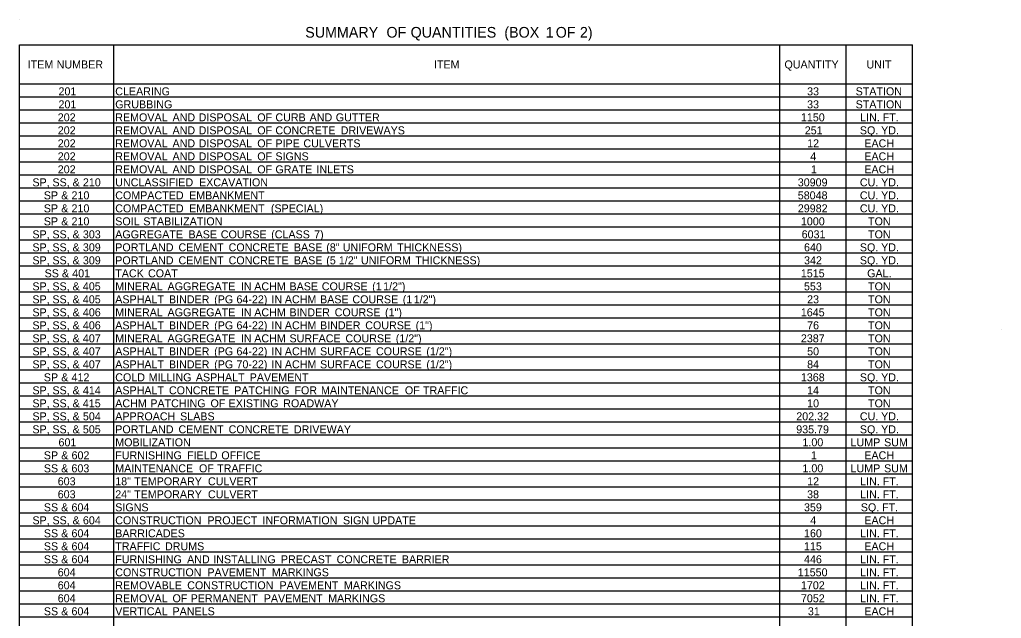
# Model space of a CAD drawing. Extents: x 1197542 to 1207068, y 230488 to 237324.
# Drawn here: x 1205581 to 1206317, y 232261 to 232710 of the extents above; entities that cross this region are included whole.
import ezdxf

# ---------------------------------------------------------------- set-up
doc = ezdxf.new("R2010")
doc.units = 0
doc.layers.add('Default', color=7, linetype='Continuous')

msp = doc.modelspace()

# ---------------------------------------------------------------- linework, layer by layer
at = {"layer": 'Default'}
for p, q in [((1205581.41, 232709.91), (1205581.41, 232709.91)), ((1205581.41, 232690.9), (1205652.09, 232690.9)), ((1205581.41, 232690.9), (1206250.74, 232690.9)), ((1205581.41, 231823.15), (1205581.41, 232690.9)), ((1205652.09, 231823.15), (1205652.09, 232690.9)), ((1206151.29, 231823.15), (1206151.29, 232690.9)), ((1206201.02, 231823.15), (1206201.02, 232690.9)), ((1206201.02, 231823.15), (1206201.02, 232690.9)), ((1206250.74, 231823.15), (1206250.74, 232690.9)), ((1205581.41, 232661.65), (1206250.74, 232661.65)), ((1205652.09, 231823.15), (1205652.09, 232661.65)), ((1206151.29, 231823.15), (1206151.29, 232661.65)), ((1205581.41, 232651.9), (1206250.74, 232651.9)), ((1205581.41, 232642.15), (1206250.74, 232642.15)), ((1205581.41, 232632.4), (1206250.74, 232632.4)), ((1205581.41, 232622.65), (1206250.74, 232622.65)), ((1205581.41, 232612.9), (1206250.74, 232612.9)), ((1205581.41, 232603.15), (1206250.74, 232603.15)), ((1205581.41, 232593.4), (1206250.74, 232593.4)), ((1205581.41, 232583.65), (1206250.74, 232583.65)), ((1205581.41, 232573.9), (1206250.74, 232573.9)), ((1205581.41, 232564.15), (1206250.74, 232564.15)), ((1205581.41, 232554.4), (1206250.74, 232554.4)), ((1205581.41, 232544.65), (1206250.74, 232544.65)), ((1205581.41, 232534.9), (1206250.74, 232534.9)), ((1205581.41, 232525.15), (1206250.74, 232525.15)), ((1205581.41, 232515.4), (1206250.74, 232515.4)), ((1205581.41, 232505.65), (1206250.74, 232505.65)), ((1205581.41, 232495.9), (1206250.74, 232495.9)), ((1205581.41, 232486.15), (1206250.74, 232486.15)), ((1206317.3, 232477.8), (1206317.3, 232477.8)), ((1205581.41, 232476.4), (1206250.74, 232476.4)), ((1205581.41, 232466.65), (1206250.74, 232466.65)), ((1205581.41, 232456.9), (1206250.74, 232456.9)), ((1205581.41, 232447.15), (1206250.74, 232447.15)), ((1205581.41, 232437.4), (1206250.74, 232437.4)), ((1205581.41, 232427.65), (1206250.74, 232427.65)), ((1205581.41, 232417.9), (1206250.74, 232417.9)), ((1205581.41, 232408.15), (1206250.74, 232408.15)), ((1205581.41, 232398.4), (1206250.74, 232398.4)), ((1205581.41, 232388.65), (1206250.74, 232388.65)), ((1205581.41, 232378.9), (1206250.74, 232378.9)), ((1205581.41, 232369.15), (1206250.74, 232369.15)), ((1205581.41, 232359.4), (1206250.74, 232359.4)), ((1205581.41, 232349.65), (1206250.74, 232349.65)), ((1205581.41, 232339.9), (1206250.74, 232339.9)), ((1205581.41, 232330.15), (1206250.74, 232330.15)), ((1205581.41, 232320.4), (1206250.74, 232320.4)), ((1205581.41, 232310.65), (1206250.74, 232310.65)), ((1205581.41, 232300.9), (1206250.74, 232300.9)), ((1205581.41, 232291.15), (1206250.74, 232291.15)), ((1205581.41, 232281.4), (1206250.74, 232281.4)), ((1205581.41, 232271.65), (1206250.74, 232271.65)), ((1205581.41, 232261.9), (1206250.74, 232261.9))]:
    msp.add_line(p, q, dxfattribs=at)

# ---------------------------------------------------------------- texts
for s, height, p in [(' SUMMARY', 8, (1205792.52, 232696.41)), (' OF', 8, (1205853.4, 232696.41)), (' QUANTITIES', 8, (1205871.51, 232696.41)), (' (BOX', 8, (1205941.76, 232696.41)), (' 1', 8, (1205972.79, 232696.41)), (' OF', 8, (1205980.3, 232696.41)), (' 2)', 8, (1205998.41, 232696.41)), ('ITEM', 6, (1205587.49, 232673.28)), (' NUMBER', 6, (1205606.92, 232673.28)), ('ITEM', 6, (1205891.98, 232673.28)), ('QUANTITY', 6, (1206154.72, 232673.28)), ('UNIT', 6, (1206216.19, 232673.28)), ('201', 6, (1205610.53, 232653.1)), ('CLEARING', 6, (1205653.07, 232653.1)), ('33', 6, (1206171.69, 232653.1)), ('STATION', 6, (1206208.06, 232653.1)), ('201', 6, (1205610.53, 232643.35)), ('GRUBBING', 6, (1205653.07, 232643.35)), ('33', 6, (1206171.69, 232643.35)), ('STATION', 6, (1206208.06, 232643.35)), ('202', 6, (1205609.98, 232633.6)), ('REMOVAL', 6, (1205653.07, 232633.6)), (' AND', 6, (1205693.77, 232633.6)), (' DISPOSAL', 6, (1205713.35, 232633.6)), (' OF', 6, (1205757.32, 232633.6)), (' CURB', 6, (1205770.9, 232633.6)), (' AND', 6, (1205796.54, 232633.6)), (' GUTTER', 6, (1205816.12, 232633.6)), ('1150', 6, (1206167.04, 232633.6)), ('LIN.', 6, (1206211.48, 232633.6)), (' FT.', 6, (1206226.12, 232633.6)), ('202', 6, (1205609.98, 232623.85)), ('REMOVAL', 6, (1205653.07, 232623.85)), (' AND', 6, (1205693.77, 232623.85)), (' DISPOSAL', 6, (1205713.35, 232623.85)), (' OF', 6, (1205757.32, 232623.85)), (' CONCRETE', 6, (1205770.9, 232623.85)), (' DRIVEWAYS', 6, (1205819.83, 232623.85)), ('251', 6, (1206169.94, 232623.85)), ('SQ.', 6, (1206211.24, 232623.85)), (' YD.', 6, (1206224.95, 232623.85)), ('202', 6, (1205609.98, 232614.1)), ('REMOVAL', 6, (1205653.07, 232614.1)), (' AND', 6, (1205693.77, 232614.1)), (' DISPOSAL', 6, (1205713.35, 232614.1)), (' OF', 6, (1205757.32, 232614.1)), (' PIPE', 6, (1205770.9, 232614.1)), (' CULVERTS', 6, (1205791.89, 232614.1)), ('12', 6, (1206171.72, 232614.1)), ('EACH', 6, (1206214.57, 232614.1)), ('202', 6, (1205609.98, 232604.35)), ('REMOVAL', 6, (1205653.07, 232604.35)), (' AND', 6, (1205693.77, 232604.35)), (' DISPOSAL', 6, (1205713.35, 232604.35)), (' OF', 6, (1205757.32, 232604.35)), (' SIGNS', 6, (1205770.9, 232604.35)), ('4', 6, (1206174.03, 232604.35)), ('EACH', 6, (1206214.57, 232604.35)), ('202', 6, (1205609.98, 232594.6)), ('REMOVAL', 6, (1205653.07, 232594.6)), (' AND', 6, (1205693.77, 232594.6)), (' DISPOSAL', 6, (1205713.35, 232594.6)), (' OF', 6, (1205757.32, 232594.6)), (' GRATE', 6, (1205770.9, 232594.6)), (' INLETS', 6, (1205801.67, 232594.6)), ('1', 6, (1206174.6, 232594.6)), ('EACH', 6, (1206214.57, 232594.6)), ('SP,', 6, (1205591, 232584.85)), (' SS,', 6, (1205603.77, 232584.85)), (' &', 6, (1205618.86, 232584.85)), (' 210', 6, (1205626.59, 232584.85)), ('UNCLASSIFIED', 6, (1205653.07, 232584.85)), (' EXCAVATION', 6, (1205713.65, 232584.85)), ('30909', 6, (1206164.69, 232584.85)), ('CU.', 6, (1206211.24, 232584.85)), (' YD.', 6, (1206224.95, 232584.85)), ('SP', 6, (1205599.52, 232575.1)), (' &', 6, (1205610.34, 232575.1)), (' 210', 6, (1205618.07, 232575.1)), ('COMPACTED', 6, (1205653.07, 232575.1)), (' EMBANKMENT', 6, (1205706.19, 232575.1)), ('58048', 6, (1206164.69, 232575.1)), ('CU.', 6, (1206211.24, 232575.1)), (' YD.', 6, (1206224.95, 232575.1)), ('SP', 6, (1205599.52, 232565.35)), (' &', 6, (1205610.34, 232565.35)), (' 210', 6, (1205618.07, 232565.35)), ('COMPACTED', 6, (1205653.07, 232565.35)), (' EMBANKMENT', 6, (1205706.19, 232565.35)), (' (SPECIAL)', 6, (1205767.51, 232565.35)), ('29982', 6, (1206164.73, 232565.35)), ('CU.', 6, (1206211.24, 232565.35)), (' YD.', 6, (1206224.95, 232565.35)), ('SP', 6, (1205599.52, 232555.6)), (' &', 6, (1205610.34, 232555.6)), (' 210', 6, (1205618.07, 232555.6)), ('SOIL', 6, (1205653.07, 232555.6)), (' STABILIZATION', 6, (1205671.87, 232555.6)), ('1000', 6, (1206167.04, 232555.6)), ('TON', 6, (1206217.37, 232555.6)), ('SP,', 6, (1205590.99, 232545.85)), (' SS,', 6, (1205603.76, 232545.85)), (' &', 6, (1205618.85, 232545.85)), (' 303', 6, (1205626.58, 232545.85)), ('AGGREGATE', 6, (1205653.07, 232545.85)), (' BASE', 6, (1205705.73, 232545.85)), (' COURSE', 6, (1205729.98, 232545.85)), (' (CLASS', 6, (1205767.74, 232545.85)), (' 7)', 6, (1205799.91, 232545.85)), ('6031', 6, (1206167.61, 232545.85)), ('TON', 6, (1206217.37, 232545.85)), ('SP,', 6, (1205590.98, 232536.1)), (' SS,', 6, (1205603.75, 232536.1)), (' &', 6, (1205618.85, 232536.1)), (' 309', 6, (1205626.58, 232536.1)), ('PORTLAND', 6, (1205653.07, 232536.1)), (' CEMENT', 6, (1205698.27, 232536.1)), (' CONCRETE', 6, (1205735.83, 232536.1)), (' BASE', 6, (1205784.76, 232536.1)), (' (8"', 6, (1205809.01, 232536.1)), (' UNIFORM', 6, (1205821.37, 232536.1)), (' THICKNESS)', 6, (1205862.19, 232536.1)), ('640', 6, (1206169.37, 232536.1)), ('SQ.', 6, (1206211.24, 232536.1)), (' YD.', 6, (1206224.95, 232536.1)), ('SP,', 6, (1205590.98, 232526.35)), (' SS,', 6, (1205603.75, 232526.35)), (' &', 6, (1205618.85, 232526.35)), (' 309', 6, (1205626.58, 232526.35)), ('PORTLAND', 6, (1205653.07, 232526.35)), (' CEMENT', 6, (1205698.27, 232526.35)), (' CONCRETE', 6, (1205735.83, 232526.35)), (' BASE', 6, (1205784.76, 232526.35)), (' (5', 6, (1205809.01, 232526.35)), (' 1/2"', 6, (1205818.46, 232526.35)), (' UNIFORM', 6, (1205835.02, 232526.35)), (' THICKNESS)', 6, (1205875.83, 232526.35)), ('342', 6, (1206169.39, 232526.35)), ('SQ.', 6, (1206211.24, 232526.35)), (' YD.', 6, (1206224.95, 232526.35)), ('SS', 6, (1205600.13, 232516.6)), (' &', 6, (1205610.87, 232516.6)), (' 401', 6, (1205618.6, 232516.6)), ('TACK', 6, (1205653.07, 232516.6)), (' COAT', 6, (1205675.41, 232516.6)), ('1515', 6, (1206167, 232516.6)), ('GAL.', 6, (1206216.7, 232516.6)), ('SP,', 6, (1205590.97, 232506.85)), (' SS,', 6, (1205603.73, 232506.85)), (' &', 6, (1205618.83, 232506.85)), (' 405', 6, (1205626.56, 232506.85)), ('MINERAL', 6, (1205653.07, 232506.85)), (' AGGREGATE', 6, (1205690.04, 232506.85)), (' IN', 6, (1205745.03, 232506.85)), (' ACHM', 6, (1205755.05, 232506.85)), (' BASE', 6, (1205781.44, 232506.85)), (' COURSE', 6, (1205805.69, 232506.85)), (' (1', 6, (1205843.44, 232506.85)), (' 1/2")', 6, (1205851.68, 232506.85)), ('553', 6, (1206169.36, 232506.85)), ('TON', 6, (1206217.37, 232506.85)), ('SP,', 6, (1205590.97, 232497.1)), (' SS,', 6, (1205603.73, 232497.1)), (' &', 6, (1205618.83, 232497.1)), (' 405', 6, (1205626.56, 232497.1)), ('ASPHALT', 6, (1205653.07, 232497.1)), (' BINDER', 6, (1205691.11, 232497.1)), (' (PG', 6, (1205725, 232497.1)), (' 64-22)', 6, (1205741.71, 232497.1)), (' IN', 6, (1205767.95, 232497.1)), (' ACHM', 6, (1205777.97, 232497.1)), (' BASE', 6, (1205804.36, 232497.1)), (' COURSE', 6, (1205828.61, 232497.1)), (' (1', 6, (1205866.36, 232497.1)), (' 1/2")', 6, (1205874.6, 232497.1)), ('23', 6, (1206171.69, 232497.1)), ('TON', 6, (1206217.37, 232497.1)), ('SP,', 6, (1205590.99, 232487.35)), (' SS,', 6, (1205603.76, 232487.35)), (' &', 6, (1205618.85, 232487.35)), (' 406', 6, (1205626.58, 232487.35)), ('MINERAL', 6, (1205653.07, 232487.35)), (' AGGREGATE', 6, (1205690.04, 232487.35)), (' IN', 6, (1205745.03, 232487.35)), (' ACHM', 6, (1205755.05, 232487.35)), (' BINDER', 6, (1205781.44, 232487.35)), (' COURSE', 6, (1205815.33, 232487.35)), (' (1")', 6, (1205853.08, 232487.35)), ('1645', 6, (1206167, 232487.35)), ('TON', 6, (1206217.37, 232487.35)), ('SP,', 6, (1205590.99, 232477.6)), (' SS,', 6, (1205603.76, 232477.6)), (' &', 6, (1205618.85, 232477.6)), (' 406', 6, (1205626.58, 232477.6)), ('ASPHALT', 6, (1205653.07, 232477.6)), (' BINDER', 6, (1205691.11, 232477.6)), (' (PG', 6, (1205725, 232477.6)), (' 64-22)', 6, (1205741.71, 232477.6)), (' IN', 6, (1205767.95, 232477.6)), (' ACHM', 6, (1205777.97, 232477.6)), (' BINDER', 6, (1205804.36, 232477.6)), (' COURSE', 6, (1205838.25, 232477.6)), (' (1")', 6, (1205876, 232477.6)), ('76', 6, (1206171.69, 232477.6)), ('TON', 6, (1206217.37, 232477.6)), ('SP,', 6, (1205590.99, 232467.85)), (' SS,', 6, (1205603.76, 232467.85)), (' &', 6, (1205618.85, 232467.85)), (' 407', 6, (1205626.58, 232467.85)), ('MINERAL', 6, (1205653.07, 232467.85)), (' AGGREGATE', 6, (1205690.04, 232467.85)), (' IN', 6, (1205745.03, 232467.85)), (' ACHM', 6, (1205755.05, 232467.85)), (' SURFACE', 6, (1205781.44, 232467.85)), (' COURSE', 6, (1205823.38, 232467.85)), (' (1/2")', 6, (1205861.13, 232467.85)), ('2387', 6, (1206167.03, 232467.85)), ('TON', 6, (1206217.37, 232467.85)), ('SP,', 6, (1205590.99, 232458.1)), (' SS,', 6, (1205603.76, 232458.1)), (' &', 6, (1205618.85, 232458.1)), (' 407', 6, (1205626.58, 232458.1)), ('ASPHALT', 6, (1205653.07, 232458.1)), (' BINDER', 6, (1205691.11, 232458.1)), (' (PG', 6, (1205725, 232458.1)), (' 64-22)', 6, (1205741.71, 232458.1)), (' IN', 6, (1205767.95, 232458.1)), (' ACHM', 6, (1205777.97, 232458.1)), (' SURFACE', 6, (1205804.36, 232458.1)), (' COURSE', 6, (1205846.3, 232458.1)), (' (1/2")', 6, (1205884.05, 232458.1)), ('50', 6, (1206171.7, 232458.1)), ('TON', 6, (1206217.37, 232458.1)), ('SP,', 6, (1205590.99, 232448.35)), (' SS,', 6, (1205603.76, 232448.35)), (' &', 6, (1205618.85, 232448.35)), (' 407', 6, (1205626.58, 232448.35)), ('ASPHALT', 6, (1205653.07, 232448.35)), (' BINDER', 6, (1205691.11, 232448.35)), (' (PG', 6, (1205725, 232448.35)), (' 70-22)', 6, (1205741.71, 232448.35)), (' IN', 6, (1205767.95, 232448.35)), (' ACHM', 6, (1205777.97, 232448.35)), (' SURFACE', 6, (1205804.36, 232448.35)), (' COURSE', 6, (1205846.3, 232448.35)), (' (1/2")', 6, (1205884.05, 232448.35)), ('84', 6, (1206171.7, 232448.35)), ('TON', 6, (1206217.37, 232448.35)), ('SP', 6, (1205599.54, 232438.6)), (' &', 6, (1205610.36, 232438.6)), (' 412', 6, (1205618.09, 232438.6)), ('COLD', 6, (1205653.07, 232438.6)), (' MILLING', 6, (1205675.91, 232438.6)), (' ASPHALT', 6, (1205711.25, 232438.6)), (' PAVEMENT', 6, (1205751.62, 232438.6)), ('1368', 6, (1206167.02, 232438.6)), ('SQ.', 6, (1206211.24, 232438.6)), (' YD.', 6, (1206224.95, 232438.6)), ('SP,', 6, (1205591, 232428.85)), (' SS,', 6, (1205603.77, 232428.85)), (' &', 6, (1205618.87, 232428.85)), (' 414', 6, (1205626.6, 232428.85)), ('ASPHALT', 6, (1205653.07, 232428.85)), (' CONCRETE', 6, (1205691.11, 232428.85)), (' PATCHING', 6, (1205740.04, 232428.85)), (' FOR', 6, (1205785.16, 232428.85)), (' MAINTENANCE', 6, (1205805.07, 232428.85)), (' OF', 6, (1205867.97, 232428.85)), (' TRAFFIC', 6, (1205881.56, 232428.85)), ('14', 6, (1206171.7, 232428.85)), ('TON', 6, (1206217.37, 232428.85)), ('SP,', 6, (1205590.97, 232419.1)), (' SS,', 6, (1205603.73, 232419.1)), (' &', 6, (1205618.83, 232419.1)), (' 415', 6, (1205626.56, 232419.1)), ('ACHM', 6, (1205653.07, 232419.1)), (' PATCHING', 6, (1205677.12, 232419.1)), (' OF', 6, (1205722.25, 232419.1)), (' EXISTING', 6, (1205735.83, 232419.1)), (' ROADWAY', 6, (1205776.77, 232419.1)), ('10', 6, (1206171.7, 232419.1)), ('TON', 6, (1206217.37, 232419.1)), ('SP,', 6, (1205591, 232409.35)), (' SS,', 6, (1205603.77, 232409.35)), (' &', 6, (1205618.87, 232409.35)), (' 504', 6, (1205626.6, 232409.35)), ('APPROACH', 6, (1205653.07, 232409.35)), (' SLABS', 6, (1205699.45, 232409.35)), ('202.32', 6, (1206163.56, 232409.35)), ('CU.', 6, (1206211.24, 232409.35)), (' YD.', 6, (1206224.95, 232409.35)), ('SP,', 6, (1205590.97, 232399.6)), (' SS,', 6, (1205603.73, 232399.6)), (' &', 6, (1205618.83, 232399.6)), (' 505', 6, (1205626.56, 232399.6)), ('PORTLAND', 6, (1205653.07, 232399.6)), (' CEMENT', 6, (1205698.27, 232399.6)), (' CONCRETE', 6, (1205735.83, 232399.6)), (' DRIVEWAY', 6, (1205784.76, 232399.6)), ('935.79', 6, (1206163.53, 232399.6)), ('SQ.', 6, (1206211.24, 232399.6)), (' YD.', 6, (1206224.95, 232399.6)), ('601', 6, (1205610.53, 232389.85)), ('MOBILIZATION', 6, (1205653.07, 232389.85)), ('1.00', 6, (1206168.2, 232389.85)), ('LUMP', 6, (1206204.25, 232389.85)), (' SUM', 6, (1206227.18, 232389.85)), ('SP', 6, (1205599.54, 232380.1)), (' &', 6, (1205610.36, 232380.1)), (' 602', 6, (1205618.09, 232380.1)), ('FURNISHING', 6, (1205653.07, 232380.1)), (' FIELD', 6, (1205704.71, 232380.1)), (' OFFICE', 6, (1205730.35, 232380.1)), ('1', 6, (1206174.6, 232380.1)), ('EACH', 6, (1206214.57, 232380.1)), ('SS', 6, (1205599.55, 232370.35)), (' &', 6, (1205610.29, 232370.35)), (' 603', 6, (1205618.02, 232370.35)), ('MAINTENANCE', 6, (1205653.07, 232370.35)), (' OF', 6, (1205713.64, 232370.35)), (' TRAFFIC', 6, (1205727.23, 232370.35)), ('1.00', 6, (1206168.2, 232370.35)), ('LUMP', 6, (1206204.25, 232370.35)), (' SUM', 6, (1206227.18, 232370.35)), ('603', 6, (1205609.95, 232360.6)), ('18"', 6, (1205653.07, 232360.6)), (' TEMPORARY', 6, (1205664.97, 232360.6)), (' CULVERT', 6, (1205720.34, 232360.6)), ('12', 6, (1206171.72, 232360.6)), ('LIN.', 6, (1206211.48, 232360.6)), (' FT.', 6, (1206226.12, 232360.6)), ('603', 6, (1205609.95, 232350.85)), ('24"', 6, (1205653.07, 232350.85)), (' TEMPORARY', 6, (1205664.97, 232350.85)), (' CULVERT', 6, (1205720.34, 232350.85)), ('38', 6, (1206171.68, 232350.85)), ('LIN.', 6, (1206211.48, 232350.85)), (' FT.', 6, (1206226.12, 232350.85)), ('SS', 6, (1205599.56, 232341.1)), (' &', 6, (1205610.31, 232341.1)), (' 604', 6, (1205618.04, 232341.1)), ('SIGNS', 6, (1205653.07, 232341.1)), ('359', 6, (1206169.35, 232341.1)), ('SQ.', 6, (1206211.94, 232341.1)), (' FT.', 6, (1206225.65, 232341.1)), ('SP,', 6, (1205591, 232331.35)), (' SS,', 6, (1205603.77, 232331.35)), (' &', 6, (1205618.87, 232331.35)), (' 604', 6, (1205626.6, 232331.35)), ('CONSTRUCTION', 6, (1205653.07, 232331.35)), (' PROJECT', 6, (1205719.92, 232331.35)), (' INFORMATION', 6, (1205761.21, 232331.35)), (' SIGN', 6, (1205821.53, 232331.35)), (' UPDATE', 6, (1205843.67, 232331.35)), ('4', 6, (1206174.03, 232331.35)), ('EACH', 6, (1206214.57, 232331.35)), ('SS', 6, (1205599.56, 232321.6)), (' &', 6, (1205610.31, 232321.6)), (' 604', 6, (1205618.04, 232321.6)), ('BARRICADES', 6, (1205653.07, 232321.6)), ('160', 6, (1206169.37, 232321.6)), ('LIN.', 6, (1206211.48, 232321.6)), (' FT.', 6, (1206226.12, 232321.6)), ('SS', 6, (1205599.56, 232311.85)), (' &', 6, (1205610.31, 232311.85)), (' 604', 6, (1205618.04, 232311.85)), ('TRAFFIC', 6, (1205653.07, 232311.85)), (' DRUMS', 6, (1205688.13, 232311.85)), ('115', 6, (1206169.33, 232311.85)), ('EACH', 6, (1206214.57, 232311.85)), ('SS', 6, (1205599.56, 232302.1)), (' &', 6, (1205610.31, 232302.1)), (' 604', 6, (1205618.04, 232302.1)), ('FURNISHING', 6, (1205653.07, 232302.1)), (' AND', 6, (1205704.71, 232302.1)), (' INSTALLING', 6, (1205724.29, 232302.1)), (' PRECAST', 6, (1205775.01, 232302.1)), (' CONCRETE', 6, (1205816.77, 232302.1)), (' BARRIER', 6, (1205865.7, 232302.1)), ('446', 6, (1206169.36, 232302.1)), ('LIN.', 6, (1206211.48, 232302.1)), (' FT.', 6, (1206226.12, 232302.1)), ('604', 6, (1205609.96, 232292.35)), ('CONSTRUCTION', 6, (1205653.07, 232292.35)), (' PAVEMENT', 6, (1205719.92, 232292.35)), (' MARKINGS', 6, (1205768.2, 232292.35)), ('11550', 6, (1206164.71, 232292.35)), ('LIN.', 6, (1206211.48, 232292.35)), (' FT.', 6, (1206226.12, 232292.35)), ('604', 6, (1205609.96, 232282.6)), ('REMOVABLE', 6, (1205653.07, 232282.6)), (' CONSTRUCTION', 6, (1205704.8, 232282.6)), (' PAVEMENT', 6, (1205773.98, 232282.6)), (' MARKINGS', 6, (1205822.27, 232282.6)), ('1702', 6, (1206167.06, 232282.6)), ('LIN.', 6, (1206211.48, 232282.6)), (' FT.', 6, (1206226.12, 232282.6)), ('604', 6, (1205609.96, 232272.85)), ('REMOVAL', 6, (1205653.07, 232272.85)), (' OF', 6, (1205693.77, 232272.85)), (' PERMANENT', 6, (1205707.36, 232272.85)), (' PAVEMENT', 6, (1205762.16, 232272.85)), (' MARKINGS', 6, (1205810.44, 232272.85)), ('7052', 6, (1206167.06, 232272.85)), ('LIN.', 6, (1206211.48, 232272.85)), (' FT.', 6, (1206226.12, 232272.85)), ('SS', 6, (1205599.56, 232263.1)), (' &', 6, (1205610.31, 232263.1)), (' 604', 6, (1205618.04, 232263.1)), ('VERTICAL', 6, (1205653.07, 232263.1)), (' PANELS', 6, (1205693.77, 232263.1)), ('31', 6, (1206172.27, 232263.1)), ('EACH', 6, (1206214.57, 232263.1))]:
    msp.add_text(s, height=height, dxfattribs=at).set_placement(p)

doc.saveas('drawing.dxf')
